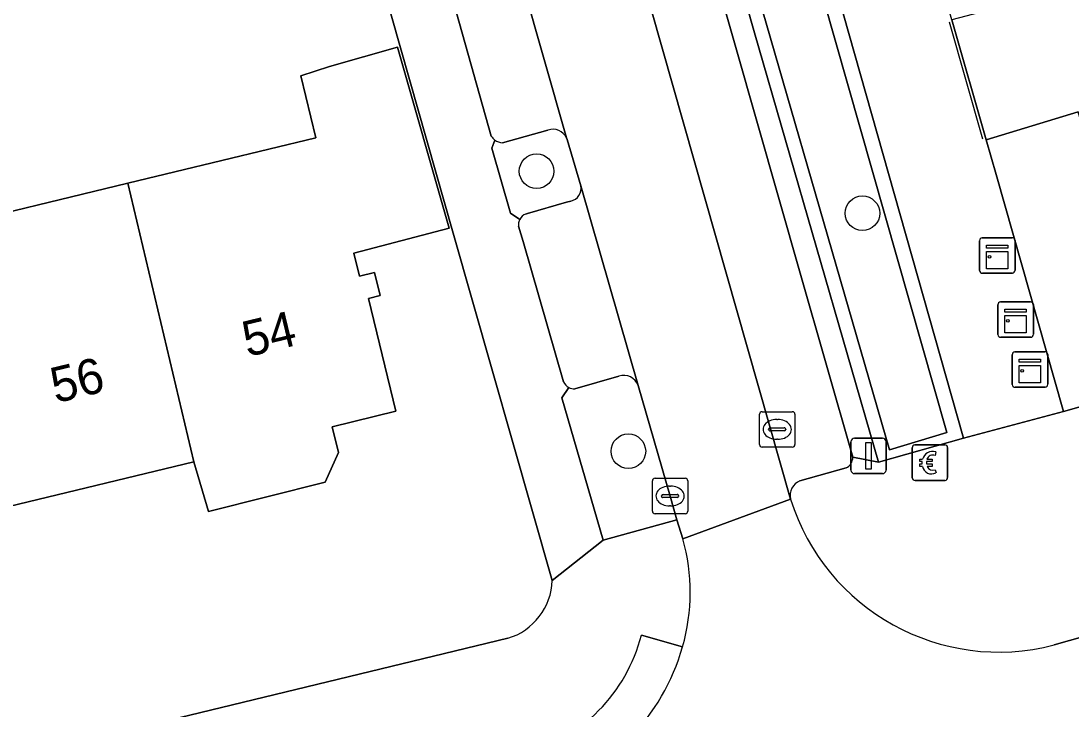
# Model space of a CAD drawing. Extents: x 159716 to 160783, y 383290 to 384031.
# Drawn here: x 160234.64 to 160264.28, y 383580.67 to 383600.11 of the extents above; entities that cross this region are included whole.
import ezdxf

# ---------------------------------------------------------------- set-up
doc = ezdxf.new("R2010")
doc.units = 0
for name, color, linetype in [('IMGEO_Betaalautomaat', 7, 'Continuous'), ('IMGEO_Boom', 7, 'Continuous'), ('IMGEO_Erf', 7, 'Continuous'), ('IMGEO_Groenvoorziening', 7, 'Continuous'), ('IMGEO_Kast', 7, 'Continuous'), ('IMGEO_Kolk', 7, 'Continuous'), ('IMGEO_Lichtmast', 7, 'Continuous'), ('IMGEO_Muur', 7, 'Continuous'), ('IMGEO_Pand', 7, 'Continuous'), ('IMGEO_Pand_nummerreeks', 7, 'Continuous'), ('IMGEO_Parkeervlak_open', 7, 'Continuous'), ('IMGEO_Rijbaan_lokaal_open', 7, 'Continuous'), ('IMGEO_Voetpad_open', 7, 'Continuous')]:
    doc.layers.add(name, color=color, linetype=linetype)

msp = doc.modelspace()

# ---------------------------------------------------------------- linework, layer by layer
at = {"layer": 'IMGEO_Betaalautomaat'}
for p, q in [((160259.877, 383588.145), (160260.718, 383588.145)), ((160260.718, 383588.145), (160259.877, 383588.145)), ((160259.802, 383587.221), (160259.802, 383588.062)), ((160259.802, 383588.062), (160259.802, 383587.221)), ((160260.464, 383587.95), (160260.447, 383587.85)), ((160260.801, 383588.071), (160260.801, 383587.23)), ((160260.801, 383587.23), (160260.801, 383588.071)), ((160260.085, 383587.609), (160260.085, 383587.677)), ((160260.206, 383587.677), (160260.206, 383587.609)), ((160260.451, 383587.444), (160260.473, 383587.357)), ((160260.727, 383587.146), (160259.886, 383587.146)), ((160259.886, 383587.146), (160260.727, 383587.146))]:
    msp.add_line(p, q, dxfattribs=at)
for points in [[(160260.085, 383587.677), (160260.016, 383587.677), (160260.016, 383587.746), (160260.095, 383587.746)], [(160260.09, 383587.54), (160260.016, 383587.54), (160260.016, 383587.609), (160260.085, 383587.609)], [(160260.217, 383587.746), (160260.364, 383587.746), (160260.364, 383587.677), (160260.206, 383587.677)], [(160260.206, 383587.609), (160260.364, 383587.609), (160260.364, 383587.54), (160260.22, 383587.54)]]:
    msp.add_lwpolyline(points, dxfattribs=at)
for centre, radius, start, end in [((160259.88, 383588.068), 0.0779, 92.4484, 184.2845), ((160259.88, 383588.068), 0.0779, 92.4484, 184.2845), ((160260.724, 383588.068), 0.0779, 2.4484, 94.2845), ((160260.724, 383588.068), 0.0779, 2.4484, 94.2845), ((160260.378, 383587.67), 0.293, 73.014, 165.0139), ((160260.384, 383587.683), 0.179, 69.3236, 159.5683), ((160260.351, 383587.595), 0.267, 191.8096, 297.0389), ((160260.384, 383587.61), 0.179, 202.7625, 291.8693), ((160259.88, 383587.224), 0.0779, 182.4484, 274.2845), ((160259.88, 383587.224), 0.0779, 182.4484, 274.2845), ((160260.724, 383587.224), 0.0779, 272.4484, 4.2845), ((160260.724, 383587.224), 0.0779, 272.4484, 4.2845)]:
    msp.add_arc(centre, radius, start, end, dxfattribs=at)
at = {"layer": 'IMGEO_Boom'}
for centre in [(160249.196, 383595.872), (160258.395, 383594.685), (160251.786, 383587.968)]:
    msp.add_circle(centre, 0.489, dxfattribs=at)
at = {"layer": 'IMGEO_Erf'}
for points in [[(160265.403, 383608.814), (160258.939, 383606.835), (160260.319, 383602.27), (160262.4, 383602.938), (160263.038, 383600.712), (160260.921, 383600.141), (160261.887, 383596.76), (160264.491, 383597.546)], [(160249.638, 383584.324), (160246.837, 383594.126), (160244.866, 383601.082)], [(160232.214, 383594.222), (160237.657, 383595.534), (160242.961, 383596.813), (160242.539, 383598.562), (160243.347, 383598.827), (160245.27, 383599.376), (160246.73, 383594.262), (160244.035, 383593.563), (160244.192, 383592.911), (160244.619, 383593.015), (160244.777, 383592.364), (160244.446, 383592.284), (160245.222, 383589.101), (160243.422, 383588.662), (160243.6, 383587.933), (160243.222, 383587.092), (160239.929, 383586.272), (160239.518, 383587.669), (160234.297, 383586.411)], [(160210.673, 383573.568), (160248.382, 383582.689)]]:
    msp.add_lwpolyline(points, dxfattribs=at)
msp.add_arc((160247.866, 383584.385), 1.773, 286.9142, 358.0232, dxfattribs=at)
at = {"layer": 'IMGEO_Groenvoorziening'}
for points in [[(160256.235, 383606.044), (160253.768, 383605.344), (160255.348, 383599.781), (160258.846, 383587.657), (160261.249, 383588.337)], [(160255.882, 383605.694), (160254.184, 383605.233), (160259.162, 383588.008), (160260.779, 383588.493)], [(160254.184, 383605.233), (160255.882, 383605.694), (160260.779, 383588.493), (160259.162, 383588.008)]]:
    msp.add_lwpolyline(points, close=True, dxfattribs=at)
for points in [[(160249.517, 383597.034), (160248.233, 383596.677)], [(160248.018, 383596.752), (160247.928, 383596.519), (160248.456, 383594.688), (160248.718, 383594.513)], [(160250.062, 383596.77), (160250.043, 383596.816)], [(160250.441, 383595.464), (160250.062, 383596.77)], [(160248.881, 383594.664), (160248.936, 383594.68), (160250.04, 383594.997), (160250.16, 383595.031)], [(160251.52, 383590.088), (160250.272, 383589.728)], [(160250.104, 383589.769), (160249.911, 383589.473), (160251.077, 383585.455), (160253.156, 383586.032), (160252.965, 383586.705), (160252.066, 383589.825)]]:
    msp.add_lwpolyline(points, dxfattribs=at)
for centre, radius, start, end in [((160249.654, 383596.62), 0.436, 26.7268, 108.2503), ((160248.245, 383597.058), 0.381, 233.3998, 268.1388), ((160250.083, 383595.388), 0.366, 282.1013, 11.9348), ((160249.004, 383594.367), 0.321, 112.5892, 153.0336), ((160251.658, 383589.676), 0.434, 20.0534, 108.5077), ((160250.268, 383590.076), 0.348, 241.8995, 270.6709)]:
    msp.add_arc(centre, radius, start, end, dxfattribs=at)
at = {"layer": 'IMGEO_Kast'}
for p, q in [((160261.704, 383593.07), (160261.704, 383593.911)), ((160261.704, 383593.911), (160261.704, 383593.07)), ((160261.779, 383593.995), (160262.62, 383593.995)), ((160262.62, 383593.995), (160261.779, 383593.995)), ((160262.704, 383593.92), (160262.704, 383593.079)), ((160262.704, 383593.079), (160262.704, 383593.92)), ((160262.629, 383592.995), (160261.788, 383592.995)), ((160261.788, 383592.995), (160262.629, 383592.995)), ((160262.222, 383591.26), (160262.222, 383592.101)), ((160262.222, 383592.101), (160262.222, 383591.26)), ((160262.297, 383592.185), (160263.138, 383592.185)), ((160263.138, 383592.185), (160262.297, 383592.185)), ((160263.222, 383592.11), (160263.222, 383591.269)), ((160263.222, 383591.269), (160263.222, 383592.11)), ((160263.147, 383591.185), (160262.306, 383591.185)), ((160262.306, 383591.185), (160263.147, 383591.185)), ((160262.627, 383589.85), (160262.627, 383590.691)), ((160262.627, 383590.691), (160262.627, 383589.85)), ((160262.702, 383590.775), (160263.543, 383590.775)), ((160263.543, 383590.775), (160262.702, 383590.775)), ((160263.627, 383590.7), (160263.627, 383589.859)), ((160263.627, 383589.859), (160263.627, 383590.7)), ((160263.552, 383589.775), (160262.711, 383589.775)), ((160262.711, 383589.775), (160263.552, 383589.775))]:
    msp.add_line(p, q, dxfattribs=at)
for points in [[(160261.899, 383593.785), (160262.499, 383593.785), (160262.499, 383593.7), (160261.899, 383593.7), (160261.899, 383593.785)], [(160261.899, 383593.61), (160262.499, 383593.61), (160262.499, 383593.121), (160261.899, 383593.121), (160261.899, 383593.61)], [(160262.417, 383591.975), (160263.017, 383591.975), (160263.017, 383591.89), (160262.417, 383591.89), (160262.417, 383591.975)], [(160262.417, 383591.8), (160263.017, 383591.8), (160263.017, 383591.311), (160262.417, 383591.311), (160262.417, 383591.8)], [(160262.822, 383590.565), (160263.422, 383590.565), (160263.422, 383590.48), (160262.822, 383590.48), (160262.822, 383590.565)], [(160262.822, 383590.39), (160263.422, 383590.39), (160263.422, 383589.901), (160262.822, 383589.901), (160262.822, 383590.39)]]:
    msp.add_lwpolyline(points, dxfattribs=at)
for centre in [(160261.983, 383593.459), (160262.501, 383591.649), (160262.906, 383590.239)]:
    msp.add_circle(centre, 0.0377, dxfattribs=at)
for centre, start, end in [((160261.782, 383593.917), 92.4484, 184.2845), ((160261.782, 383593.917), 92.4484, 184.2845), ((160262.626, 383593.917), 2.4484, 94.2845), ((160262.626, 383593.917), 2.4484, 94.2845), ((160261.782, 383593.073), 182.4484, 274.2845), ((160261.782, 383593.073), 182.4484, 274.2845), ((160262.626, 383593.073), 272.4484, 4.2845), ((160262.626, 383593.073), 272.4484, 4.2845), ((160262.3, 383592.107), 92.4484, 184.2845), ((160262.3, 383592.107), 92.4484, 184.2845), ((160263.144, 383592.107), 2.4484, 94.2845), ((160263.144, 383592.107), 2.4484, 94.2845), ((160262.3, 383591.263), 182.4484, 274.2845), ((160262.3, 383591.263), 182.4484, 274.2845), ((160263.144, 383591.263), 272.4484, 4.2845), ((160263.144, 383591.263), 272.4484, 4.2845), ((160262.705, 383590.697), 92.4484, 184.2845), ((160262.705, 383590.697), 92.4484, 184.2845), ((160263.549, 383590.697), 2.4484, 94.2845), ((160263.549, 383590.697), 2.4484, 94.2845), ((160262.705, 383589.853), 182.4484, 274.2845), ((160262.705, 383589.853), 182.4484, 274.2845), ((160263.549, 383589.853), 272.4484, 4.2845), ((160263.549, 383589.853), 272.4484, 4.2845)]:
    msp.add_arc(centre, 0.0779, start, end, dxfattribs=at)
at = {"layer": 'IMGEO_Kolk'}
for p, q in [((160255.564, 383589.085), (160256.416, 383589.085)), ((160255.489, 383588.159), (160255.489, 383589.011)), ((160255.977, 383588.865), (160256.002, 383588.865)), ((160256.49, 383589.011), (160256.49, 383588.159)), ((160255.748, 383588.579), (160255.748, 383588.591)), ((160256.186, 383588.542), (160255.788, 383588.542)), ((160255.791, 383588.628), (160256.189, 383588.628)), ((160256.232, 383588.591), (160256.232, 383588.579)), ((160256, 383588.305), (160255.975, 383588.305)), ((160256.416, 383588.085), (160255.564, 383588.085)), ((160252.464, 383586.279), (160252.464, 383587.131)), ((160252.539, 383587.205), (160253.391, 383587.205)), ((160252.952, 383586.985), (160252.977, 383586.985)), ((160253.465, 383587.131), (160253.465, 383586.279)), ((160252.723, 383586.699), (160252.723, 383586.711)), ((160253.161, 383586.662), (160252.763, 383586.662)), ((160252.766, 383586.748), (160253.164, 383586.748)), ((160253.207, 383586.711), (160253.207, 383586.699)), ((160252.975, 383586.425), (160252.95, 383586.425)), ((160253.391, 383586.205), (160252.539, 383586.205))]:
    msp.add_line(p, q, dxfattribs=at)
for points in [[(160255.564, 383589.085), (160256.416, 383589.085)], [(160255.489, 383588.159), (160255.489, 383589.011)], [(160256.49, 383589.011), (160256.49, 383588.159)], [(160256.416, 383588.085), (160255.564, 383588.085)], [(160252.464, 383586.279), (160252.464, 383587.131)], [(160252.539, 383587.205), (160253.391, 383587.205)], [(160253.465, 383587.131), (160253.465, 383586.279)], [(160253.391, 383586.205), (160252.539, 383586.205)]]:
    msp.add_lwpolyline(points, dxfattribs=at)
for centre, radius, start, end in [((160255.566, 383589.009), 0.0765, 91.552, 178.448), ((160255.566, 383589.009), 0.0765, 91.552, 178.448), ((160256.414, 383589.009), 0.0765, 1.552, 88.448), ((160256.414, 383589.009), 0.0765, 1.552, 88.448), ((160255.788, 383588.588), 0.0403, 85.8775, 175.7526), ((160255.785, 383588.578), 0.0366, 178.938, 274.7102), ((160256.189, 383588.585), 0.043, 264.8664, 352.4533), ((160256.193, 383588.59), 0.0386, 1.7309, 96.639), ((160255.566, 383588.161), 0.0765, 181.552, 268.448), ((160255.566, 383588.161), 0.0765, 181.552, 268.448), ((160256.414, 383588.161), 0.0765, 271.552, 358.448), ((160256.414, 383588.161), 0.0765, 271.552, 358.448), ((160252.541, 383587.129), 0.0765, 91.552, 178.448), ((160252.541, 383587.129), 0.0765, 91.552, 178.448), ((160253.389, 383587.129), 0.0765, 1.552, 88.448), ((160253.389, 383587.129), 0.0765, 1.552, 88.448), ((160252.763, 383586.708), 0.0403, 85.8775, 175.7526), ((160252.76, 383586.698), 0.0366, 178.938, 274.7102), ((160253.164, 383586.705), 0.043, 264.8664, 352.4533), ((160253.168, 383586.71), 0.0386, 1.7309, 96.639), ((160252.541, 383586.281), 0.0765, 181.552, 268.448), ((160252.541, 383586.281), 0.0765, 181.552, 268.448), ((160253.389, 383586.281), 0.0765, 271.552, 358.448), ((160253.389, 383586.281), 0.0765, 271.552, 358.448)]:
    msp.add_arc(centre, radius, start, end, dxfattribs=at)
for centre, major_axis, ratio, start_param, end_param in [((160255.976, 383588.585), (-0.387, 0.002), 0.722429, 4.712389, 7.853982), ((160256.001, 383588.585), (-0.39, 0.002), 0.717154, 1.570796, 4.712389), ((160252.951, 383586.705), (-0.387, 0.002), 0.722429, 4.712389, 7.853982), ((160252.976, 383586.705), (-0.39, 0.002), 0.717154, 1.570796, 4.712389)]:
    msp.add_ellipse(centre, major_axis=major_axis, ratio=ratio, start_param=start_param, end_param=end_param, dxfattribs=at)
at = {"layer": 'IMGEO_Lichtmast'}
for p, q in [((160258.072, 383587.436), (160258.072, 383588.236)), ((160258.072, 383588.236), (160258.072, 383587.436)), ((160258.172, 383588.336), (160258.962, 383588.336)), ((160258.962, 383588.336), (160258.172, 383588.336)), ((160259.062, 383588.236), (160259.062, 383587.436)), ((160259.062, 383587.436), (160259.062, 383588.236)), ((160258.962, 383587.336), (160258.172, 383587.336)), ((160258.172, 383587.336), (160258.962, 383587.336))]:
    msp.add_line(p, q, dxfattribs=at)
msp.add_lwpolyline([(160258.492, 383588.211), (160258.642, 383588.211), (160258.642, 383587.461), (160258.492, 383587.461), (160258.492, 383588.211)], dxfattribs=at)
for centre, start, end in [((160258.172, 383588.236), 90, 180), ((160258.172, 383588.236), 90, 180), ((160258.962, 383588.236), 0, 90), ((160258.962, 383588.236), 360, 90), ((160258.172, 383587.436), 180, 270), ((160258.172, 383587.436), 180, 270), ((160258.962, 383587.436), 270, 0), ((160258.962, 383587.436), 270, 0)]:
    msp.add_arc(centre, 0.1, start, end, dxfattribs=at)
at = {"layer": 'IMGEO_Muur'}
msp.add_lwpolyline([(160261.799, 383596.773), (160260.85, 383600.084)], dxfattribs=at)
at = {"layer": 'IMGEO_Pand'}
for points in [[(160244.619, 383593.015), (160244.192, 383592.911), (160244.035, 383593.563), (160246.73, 383594.262), (160245.27, 383599.376), (160243.347, 383598.827), (160242.539, 383598.562), (160242.961, 383596.813), (160237.657, 383595.534), (160239.518, 383587.669), (160239.929, 383586.272), (160243.222, 383587.092), (160243.6, 383587.933), (160243.422, 383588.662), (160245.222, 383589.101), (160244.446, 383592.284), (160244.777, 383592.364)], [(160266.649, 383597.125), (160264.767, 383596.585), (160264.491, 383597.546), (160261.887, 383596.76), (160262.173, 383595.776), (160264.072, 383589.089), (160268.587, 383590.379)], [(160237.657, 383595.534), (160232.214, 383594.222), (160234.109, 383586.366), (160234.297, 383586.411), (160239.518, 383587.669)]]:
    msp.add_lwpolyline(points, close=True, dxfattribs=at)
at = {"layer": 'IMGEO_Parkeervlak_open'}
for points in [[(160243.885, 383630.351), (160244.978, 383626.728), (160245.86, 383623.489), (160251.53, 383603.625), (160256.367, 383586.618)], [(160245.99, 383630.302), (160247.936, 383623.46), (160252.983, 383605.807), (160256.641, 383592.996), (160258.124, 383587.802), (160258.846, 383587.657), (160255.348, 383599.781), (160253.768, 383605.344), (160256.235, 383606.044), (160261.249, 383588.337), (160264.072, 383589.089), (160262.173, 383595.776), (160261.887, 383596.76), (160260.921, 383600.141), (160260.319, 383602.27), (160258.939, 383606.835), (160258.134, 383609.693), (160255.175, 383608.85), (160253.849, 383613.466), (160252.612, 383617.776), (160251.374, 383622.085), (160250.137, 383626.395)], [(160258.124, 383587.802), (160256.641, 383592.996), (160252.983, 383605.807), (160247.936, 383623.46)], [(160243.265, 383613.205), (160246.087, 383603.351), (160246.93, 383600.34), (160247.915, 383596.865)], [(160250.043, 383596.816), (160248.793, 383601.177), (160247.348, 383606.238)], [(160248.233, 383596.677), (160249.517, 383597.034)], [(160252.066, 383589.825), (160250.441, 383595.464)], [(160250.16, 383595.031), (160250.04, 383594.997), (160248.936, 383594.68), (160248.881, 383594.664)], [(160248.688, 383594.324), (160248.817, 383593.889), (160249.956, 383589.929)], [(160287.253, 383592.617), (160282.794, 383591.335), (160277.895, 383589.927), (160277.067, 383592.8), (160273.048, 383591.653), (160268.587, 383590.379), (160264.072, 383589.089), (160261.249, 383588.337), (160258.846, 383587.657), (160258.124, 383587.802)], [(160250.272, 383589.728), (160251.52, 383590.088)], [(160263.806, 383582.501), (160265.839, 383583.079), (160265.47, 383584.313), (160278.207, 383588.06), (160278.529, 383587.889)], [(160257.935, 383587.499), (160256.63, 383587.133)], [(160256.63, 383587.133), (160257.935, 383587.499)]]:
    msp.add_lwpolyline(points, dxfattribs=at)
for centre, radius, start, end in [((160249.654, 383596.62), 0.436, 26.7268, 108.2503), ((160248.242, 383597.059), 0.38, 210.7425, 233.9561), ((160248.245, 383597.058), 0.381, 233.3998, 268.1388), ((160250.083, 383595.388), 0.366, 282.1013, 11.9348), ((160249.004, 383594.367), 0.321, 112.5892, 153.0336), ((160248.993, 383594.372), 0.309, 152.9202, 189.0411), ((160250.27, 383590.071), 0.344, 204.3264, 241.2112), ((160251.658, 383589.676), 0.434, 20.0534, 108.5077), ((160250.268, 383590.076), 0.348, 241.8995, 270.6709), ((160257.781, 383587.805), 0.343, 296.636, 359.4553), ((160257.781, 383587.805), 0.343, 296.636, 359.4553), ((160256.801, 383586.721), 0.446, 112.555, 193.3401), ((160256.801, 383586.721), 0.446, 112.555, 193.3401), ((160262.244, 383588.459), 6.159, 197.3888, 284.6879)]:
    msp.add_arc(centre, radius, start, end, dxfattribs=at)
at = {"layer": 'IMGEO_Rijbaan_lokaal_open'}
for points in [[(160233.141, 383645.332), (160236.476, 383632.08), (160237.374, 383628.936), (160238.442, 383625.195), (160242.222, 383611.955), (160241.805, 383611.855), (160242.228, 383610.369), (160244.866, 383601.082), (160246.837, 383594.126), (160249.638, 383584.324), (160251.077, 383585.455), (160249.911, 383589.473), (160250.104, 383589.769)], [(160247.915, 383596.865), (160246.93, 383600.34), (160246.087, 383603.351), (160243.265, 383613.205)], [(160248.718, 383594.513), (160248.456, 383594.688), (160247.928, 383596.519), (160248.018, 383596.752)], [(160249.956, 383589.929), (160248.817, 383593.889), (160248.688, 383594.324)], [(160256.367, 383586.618), (160253.322, 383585.494)], [(160253.322, 383585.494), (160253.156, 383586.032), (160251.077, 383585.455), (160249.638, 383584.324)], [(160275.812, 383586.017), (160266.897, 383583.424), (160265.839, 383583.079), (160263.806, 383582.501)], [(160248.382, 383582.689), (160210.673, 383573.568), (160210.886, 383572.735), (160205.458, 383571.364), (160180.862, 383565.396), (160176.038, 383563.423)], [(160252.157, 383582.777), (160253.317, 383582.451)]]:
    msp.add_lwpolyline(points, dxfattribs=at)
msp.add_lwpolyline([(160251.53, 383603.625), (160245.86, 383623.489), (160242.673, 383622.561), (160244.345, 383616.783), (160244.986, 383614.377), (160247.348, 383606.238), (160248.793, 383601.177), (160250.043, 383596.816), (160250.062, 383596.77), (160250.441, 383595.464), (160252.066, 383589.825), (160252.965, 383586.705), (160253.156, 383586.032), (160253.322, 383585.494), (160256.367, 383586.618)], close=True, dxfattribs=at)
for centre, radius, start, end in [((160248.242, 383597.059), 0.38, 210.7425, 233.9561), ((160248.993, 383594.372), 0.309, 152.9202, 189.0411), ((160250.27, 383590.071), 0.344, 204.3264, 241.2112), ((160262.244, 383588.459), 6.159, 197.3888, 284.6879), ((160248.032, 383583.981), 5.502, 343.8514, 15.9603), ((160248.032, 383583.981), 5.502, 343.8514, 15.9603), ((160247.866, 383584.385), 1.773, 286.9142, 358.0232), ((160247.549, 383583.985), 4.764, 285.7118, 345.315), ((160247.331, 383584.176), 6.23, 288.2221, 343.9219)]:
    msp.add_arc(centre, radius, start, end, dxfattribs=at)
at = {"layer": 'IMGEO_Voetpad_open'}
msp.add_lwpolyline([(160253.317, 383582.451), (160252.157, 383582.777)], dxfattribs=at)
for centre, radius, start, end in [((160247.549, 383583.985), 4.764, 285.7118, 345.315), ((160247.331, 383584.176), 6.23, 288.2221, 343.9219)]:
    msp.add_arc(centre, radius, start, end, dxfattribs=at)

# ---------------------------------------------------------------- texts
at = {"layer": 'IMGEO_Pand_nummerreeks'}
for s, p in [('54', (160241.027, 383590.626)), ('56', (160235.611, 383589.32))]:
    msp.add_text(s, height=1, rotation=13.5505, dxfattribs=at).set_placement(p)

doc.saveas('drawing.dxf')
